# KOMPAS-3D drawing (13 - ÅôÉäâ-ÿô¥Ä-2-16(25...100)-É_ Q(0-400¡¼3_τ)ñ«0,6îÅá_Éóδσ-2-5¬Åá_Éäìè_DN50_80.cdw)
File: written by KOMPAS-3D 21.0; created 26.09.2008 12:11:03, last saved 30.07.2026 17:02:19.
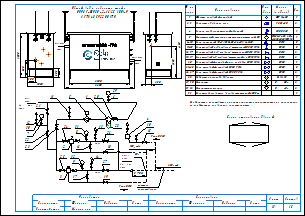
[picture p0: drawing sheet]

Sheets 1-2: A3, landscape

Document properties: Наименование: Макро:21; Автор: RaskoAdmin; Форматы листов документа: 2xA3; Полное имя файла: \\UR38nt01\Departments\КТО\КБ ПУРДГ\Заявки\Прайс-лист на типовые шкафы ГРПШ\ПУРДГ_стандарт_30_04_2026\ПУРДГ с РДНК\ПУРДГ-ШУЭО-2-16(25...100)-Р_ Q(0-400нм3_ч)до0,6МПа_Рвых-2-5кПа_РДНК_DN50_80.cdw

Title block, sheet 1: Наименование: Пункт учета газа / ПУГ-Ш-400-Р / ЛГТИ.485922.001ТУ; designation: ЛГТИ.03.4411141; sheet number: 1; Количество листов документа: 2; organisation: ООО "ЭЛЬСТЕР Газэлектроника"; Форматы листов документа: A3; stored path: C:\Рабочие документы\Компас\ПУГ\Схема.cdw; Разработал: Устинов; Проверил: Кошкин; Утвердил: Кошкин
Title block, sheet 2: sheet number: 2; stored path: D:\Рабочие документы\Заявки\ПУРДГ\ПУРДГ-ШУЭО-2-100-Р 4411220.cdw; designation, second copy: ЛГТИ.03.4411141-

Views: Вид 1, Вид 2
Referenced files: wcvoit.frw
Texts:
  Normal
  № на
  схеме
  Усл.
  обозн.
  Марка
  (модель)
  Кол.
  Фильтр газовый фланцевый
  ФГ 16-50
  Регулятор давления газа
  РДНК-50
  Клапан предохранительный сбросной
  КПС DN20
  Измерительный комплекс с ротационным счетчиком Ду50
  СГ-ЭК-Р-(0,2...2,0)-
  Кран кнопочный VE-РАСКО-НЗ-1,6-G1/2-М20
  DN15
  Кран шаровой "под приварку" штуцерный DN20 PN16
  DN20
  Кран шаровой "под приварку" штуцерный DN15 PN16
  Кран шаровой "под приварку" штуцерный п/п DN15 PN16
  Кран шаровой фланцевый с мех. приводом DN50 PN16
  Кран шаровой фланцевый DN50 PN16
  Кран шаровой фланцевый DN80 PN16
  DN50
  DN80
  Индикатор перепада давления
  Манометр
  Манометр-напоромер
  Электрообогреватель взрывозащищенный 400Вт
  Delta 15
  0...     МПа
  0...     кПа
  Общий вид и габариты шкафа
  ПУРДГ-ШУЭО-2-16(25...100)-Р
  Выход газа
  Вход газа
  logo-rasko-ge.png
  DN 1
  местное
  сопротивление
  Римп DN15
  Римп DN20
  Выход
  газа
  Р=     кПа
  Вход
  Р=       МПа
  PDI
  Схема открывания дверей
  Предприятие изготовитель может заменять комплектующие на аналогичные,
  не ухудшающие заявленных характеристик.
  Должность
  Конструктор
  Фамилия
  Подпись
  Дата
  Согласовано
  Максимкин
  Лист
  Листов
  POLYLINE_STYLE_0.18_RGB_0_0_0
  POLYLINE_STYLE_0.50_RGB_0_0_0
  POLYLINE_STYLE_0.34_RGB_0_0_0
  PHANTOM_RGB_0_0_0_SC_1_THICK_0.18
  K5LT_THIN_RGB_0_0_0_THICK_0.18
  K5LT32769_RGB_0_0_0_THICK_0.18
  K5LT12_RGB_0_0_0_SC_1_THICK_0.18
  K5LT_DASHED_RGB_0_0_0_SC_1_THICK_0.18
  ACISOTGL_RGB_0_0_0_SC_0.8_THICK_0.25
  CONTINUOUS_RGB_0_127_31_THICK_0.3
  CONTINUOUS_RGB_0_0_255_THICK_0.35
  CONTINUOUS_RGB_255_0_0_THICK_0.35
  POLYLINE_STYLE_0.25_RGB_0_0_0
  CONTINUOUS_RGB_0_0_0_THICK_0.5
  POLYLINE_STYLE_0.35_RGB_0_0_255
  CONTINUOUS_RGB_0_0_0_THICK_0.4
  CONTINUOUS_RGB_0_0_0_THICK_0.35
  НЕВИДИМАЯ_RGB_0_0_0_SC_0.3_THICK_0.25
  СONTINUOUS_RGB_0_0_0_THICK_0.25
  ОСЕВАЯ2_RGB_248_153_30_SC_0.3_THICK_0.25
  Без оформления
Dimensions and other numbers on the sheet: 1; 2, 3; 2; 4; 5; 6-10; 11-15; 16, 17; 18, 19; 20; 21-25; 26, 27; 28; 29, 30; 31, 32; 33; 1500; 250; 300; 1050; 550; 305; 2300; 4130; 2000; 2600; 5,,,7DN 1; 7; 30; 12; 21; 22; 23; 11; 6; 29; 24; 31; 8; 16; 13; 26; 18; 10; 15; 25; 32; 9; 3; 17; 14; 27; 19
